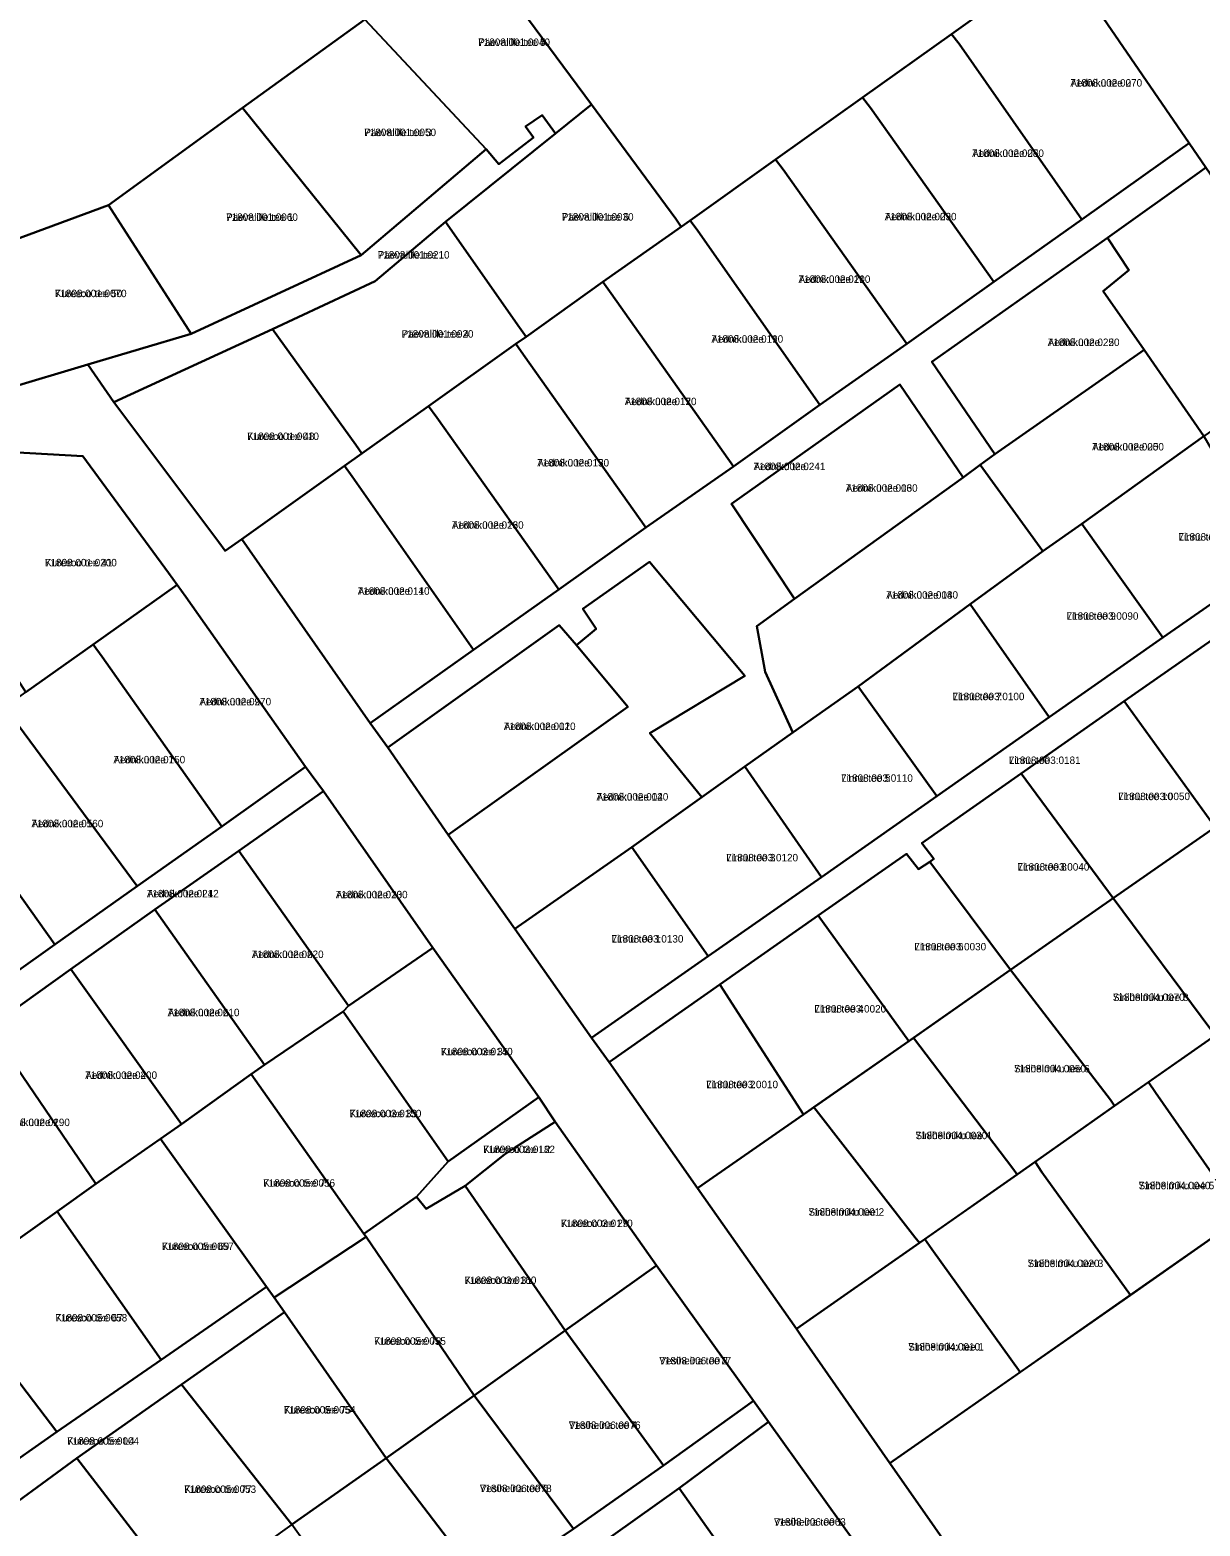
# Model space of a CAD drawing. Extents: x 529768 to 552006, y 6562269 to 6580975.
# Drawn here: x 537003.6 to 537239.9, y 6569673.6 to 6569975.7 of the extents above; entities that cross this region are included whole.
import ezdxf

# ---------------------------------------------------------------- set-up
doc = ezdxf.new("R2010")
doc.units = 0
for name, color, linetype in [('L_AADRESS', 7, 'Continuous'), ('PIIR', 7, 'Continuous'), ('TUNNUS', 7, 'Continuous')]:
    doc.layers.add(name, color=color, linetype=linetype)

msp = doc.modelspace()

# ---------------------------------------------------------------- linework, layer by layer
at = {"layer": 'PIIR'}
for points in [[(536874.54, 6569968.46), (536872.33, 6569970.82), (537004.98, 6570064.24), (537087.96, 6570044.75), (537217.62, 6570003.73), (537216.26, 6569994.13), (537211.8, 6569990.69), (537189.74, 6569974.89), (537171.78, 6569962.1), (537154.21, 6569949.58), (537136.95, 6569937.29), (537135.14, 6569936.01), (537134.04, 6569937.57), (537117.07, 6569960.7), (537092.75, 6569993.55), (537071.26, 6569977.87), (537046.54, 6569959.99), (537019.53, 6569940.36), (536982.49, 6569926.7), (536956.57, 6569916.92), (536936.23, 6569902.65)], [(537211.8, 6569990.69), (537216.26, 6569994.13), (537217.62, 6570003.73), (537232.49, 6570000.18), (537431.89, 6569969.31), (537436.12, 6569962.6), (537345.33, 6569804), (537340.93, 6569801.03), (537314.01, 6569841.27), (537303.21, 6569856.76), (537294.77, 6569869.2), (537282.21, 6569887.72), (537266.16, 6569911.4), (537241.1, 6569947.95), (537237.73, 6569952.86)], [(537092.75, 6569993.55), (537117.07, 6569960.7), (537109.79, 6569954.82), (537107.06, 6569958.54), (537103.75, 6569956.25), (537105.35, 6569953.99), (537098.33, 6569948.64), (537095.76, 6569951.67), (537071.26, 6569977.87)], [(537189.74, 6569974.89), (537211.8, 6569990.69), (537237.73, 6569952.86), (537236.38, 6569951.9), (537216.02, 6569937.45), (537191.29, 6569972.9)], [(537046.54, 6569959.99), (537071.26, 6569977.87), (537095.76, 6569951.67), (537070.53, 6569930.28)], [(537171.78, 6569962.1), (537189.74, 6569974.89), (537191.29, 6569972.9), (537216.02, 6569937.45), (537198.3, 6569924.84), (537173.36, 6569959.98)], [(537102.52, 6569915.64), (537087.53, 6569937.02), (537109.79, 6569954.82), (537117.07, 6569960.7), (537134.04, 6569937.57), (537135.14, 6569936.01), (537119.36, 6569924.86), (537103.82, 6569913.79)], [(537154.21, 6569949.58), (537171.78, 6569962.1), (537173.36, 6569959.98), (537198.3, 6569924.84), (537180.75, 6569912.38), (537155.75, 6569947.54)], [(537109.79, 6569954.82), (537087.53, 6569937.02), (537073.37, 6569924.99), (537052.62, 6569915.32), (537020.57, 6569900.6), (537015.35, 6569908.21), (537036.2, 6569914.4), (537070.53, 6569930.28), (537095.76, 6569951.67), (537098.33, 6569948.64), (537105.35, 6569953.99), (537103.75, 6569956.25), (537107.06, 6569958.54)], [(537019.53, 6569940.36), (537046.54, 6569959.99), (537070.53, 6569930.28), (537036.2, 6569914.4)], [(537115.26, 6569858.82), (537117.98, 6569854.8), (537114, 6569851.52), (537110.54, 6569855.53), (537075.93, 6569830.86), (537072.36, 6569835.79), (537093.24, 6569850.55), (537110.48, 6569862.75), (537128.03, 6569875.24), (537145.73, 6569887.59), (537163.14, 6569900.03), (537180.75, 6569912.38), (537198.3, 6569924.84), (537216.02, 6569937.45), (537236.38, 6569951.9), (537237.73, 6569952.86), (537241.1, 6569947.95), (537239.79, 6569947.01), (537221.23, 6569933.75), (537185.75, 6569908.75), (537198.5, 6569890.09), (537195.55, 6569887.91), (537192.06, 6569885.35), (537179.28, 6569904.13), (537145.28, 6569880.07), (537158.01, 6569860.85), (537150.46, 6569855.33), (537152.1, 6569846.14), (537157.71, 6569833.88), (537148.02, 6569827.01), (537139.3, 6569820.84), (537128.79, 6569833.71), (537148.02, 6569845.33), (537128.76, 6569868.32)], [(537136.95, 6569937.29), (537154.21, 6569949.58), (537155.75, 6569947.54), (537180.75, 6569912.38), (537163.14, 6569900.03), (537138.52, 6569935.16)], [(537228.61, 6569911.15), (537220.34, 6569923.01), (537225.55, 6569927.21), (537221.23, 6569933.75), (537239.79, 6569947.01), (537241.1, 6569947.95), (537266.16, 6569911.4), (537264.76, 6569910.44), (537240.71, 6569893.71)], [(536982.49, 6569926.7), (537019.53, 6569940.36), (537036.2, 6569914.4), (537015.35, 6569908.21), (536998.7, 6569903.2)], [(537069.43, 6569891.94), (537052.62, 6569915.32), (537073.37, 6569924.99), (537087.53, 6569937.02), (537102.52, 6569915.64), (537103.82, 6569913.79), (537101.78, 6569912.35), (537084.16, 6569899.8), (537070.68, 6569890.2)], [(537119.36, 6569924.86), (537135.14, 6569936.01), (537136.95, 6569937.29), (537138.52, 6569935.16), (537163.14, 6569900.03), (537145.73, 6569887.59), (537121.01, 6569922.53)], [(537225.55, 6569927.21), (537220.34, 6569923.01), (537228.61, 6569911.15), (537198.5, 6569890.09), (537185.75, 6569908.75), (537221.23, 6569933.75)], [(537101.78, 6569912.35), (537103.82, 6569913.79), (537119.36, 6569924.86), (537121.01, 6569922.53), (537145.73, 6569887.59), (537128.03, 6569875.24), (537103.34, 6569910.15)], [(537041.78, 6569872.29), (537020.57, 6569900.6), (537052.62, 6569915.32), (537069.43, 6569891.94), (537070.68, 6569890.2), (537067.2, 6569887.71), (537046.43, 6569872.94), (537043.08, 6569870.55)], [(537084.16, 6569899.8), (537101.78, 6569912.35), (537103.34, 6569910.15), (537128.03, 6569875.24), (537110.48, 6569862.75), (537085.81, 6569897.48)], [(537198.5, 6569890.09), (537228.61, 6569911.15), (537240.71, 6569893.71), (537216.03, 6569876.03), (537208.18, 6569870.5), (537195.55, 6569887.91)], [(537145.28, 6569880.07), (537179.28, 6569904.13), (537192.06, 6569885.35), (537158.01, 6569860.85)], [(537067.2, 6569887.71), (537070.68, 6569890.2), (537084.16, 6569899.8), (537085.81, 6569897.48), (537110.48, 6569862.75), (537093.24, 6569850.55), (537068.72, 6569885.54)], [(537216.03, 6569876.03), (537240.71, 6569893.71), (537255.1, 6569868.83), (537232.43, 6569853.06)], [(537001.14, 6569844.61), (536979.97, 6569876.46), (537000.05, 6569890.46), (537014.36, 6569889.68), (537031.65, 6569866.11), (537033.41, 6569863.68), (537016.43, 6569851.67), (537002.85, 6569842.04)], [(537046.43, 6569872.94), (537067.2, 6569887.71), (537068.72, 6569885.54), (537093.24, 6569850.55), (537072.36, 6569835.79), (537047.97, 6569870.72)], [(537266.5, 6569869.46), (537244.56, 6569854.13), (537224.58, 6569840.19), (537203.79, 6569825.57), (537183.73, 6569811.56), (537186.15, 6569808.37), (537185.37, 6569807.78), (537183.1, 6569806.29), (537180.68, 6569809.37), (537162.8, 6569796.92), (537142.98, 6569782.98), (537120.6, 6569767.33), (537117.06, 6569772.21), (537140.59, 6569788.71), (537163.51, 6569804.69), (537186.78, 6569821.01), (537209.48, 6569836.96), (537232.43, 6569853.06), (537255.1, 6569868.83), (537280.13, 6569886.27), (537282.21, 6569887.72), (537294.77, 6569869.2), (537292.95, 6569868.02), (537275.94, 6569857)], [(537208.18, 6569870.5), (537193.52, 6569859.79), (537170.88, 6569843.14), (537157.71, 6569833.88), (537152.1, 6569846.14), (537150.46, 6569855.33), (537158.01, 6569860.85), (537192.06, 6569885.35), (537195.55, 6569887.91)], [(537193.52, 6569859.79), (537208.18, 6569870.5), (537216.03, 6569876.03), (537232.43, 6569853.06), (537209.48, 6569836.96)], [(537088.07, 6569813.23), (537124.36, 6569839.05), (537114, 6569851.52), (537117.98, 6569854.8), (537115.26, 6569858.82), (537128.76, 6569868.32), (537148.02, 6569845.33), (537128.79, 6569833.71), (537139.3, 6569820.84), (537125.2, 6569810.72), (537101.58, 6569794.24)], [(537016.43, 6569851.67), (537033.41, 6569863.68), (537035.16, 6569861.27), (537059.3, 6569826.93), (537042.4, 6569814.87), (537018.21, 6569849.15)], [(537170.88, 6569843.14), (537193.52, 6569859.79), (537209.48, 6569836.96), (537186.78, 6569821.01)], [(537075.93, 6569830.86), (537110.54, 6569855.53), (537114, 6569851.52), (537124.36, 6569839.05), (537088.07, 6569813.23)], [(536998.59, 6569839.02), (537002.85, 6569842.04), (537016.43, 6569851.67), (537018.21, 6569849.15), (537042.4, 6569814.87), (537025.31, 6569802.87), (537000.4, 6569836.57)], [(537244.56, 6569854.13), (537263.28, 6569828.91), (537242.99, 6569814.75), (537224.58, 6569840.19)], [(537148.02, 6569827.01), (537157.71, 6569833.88), (537170.88, 6569843.14), (537186.78, 6569821.01), (537163.51, 6569804.69)], [(537224.58, 6569840.19), (537242.99, 6569814.75), (537222.41, 6569800.4), (537203.79, 6569825.57)], [(536982.61, 6569827.71), (536983.08, 6569828.05), (536998.59, 6569839.02), (537000.4, 6569836.57), (537025.31, 6569802.87), (537008.71, 6569791.05), (536984.39, 6569825.21)], [(536965.89, 6569815.87), (536982.61, 6569827.71), (536984.39, 6569825.21), (537008.71, 6569791.05), (536991.72, 6569779.05), (536967.63, 6569813.38)], [(537062.94, 6569822.02), (537045.82, 6569810), (537028.9, 6569798.1), (537011.91, 6569786.06), (536995.4, 6569774.32), (536990.47, 6569774.25), (536991.72, 6569779.05), (537008.71, 6569791.05), (537025.31, 6569802.87), (537042.4, 6569814.87), (537059.3, 6569826.93)], [(537125.2, 6569810.72), (537139.3, 6569820.84), (537148.02, 6569827.01), (537163.51, 6569804.69), (537140.59, 6569788.71)], [(537186.15, 6569808.37), (537183.73, 6569811.56), (537203.79, 6569825.57), (537222.41, 6569800.4), (537201.67, 6569785.93), (537185.37, 6569807.78)], [(537062.94, 6569822.02), (537084.99, 6569790.38), (537067.99, 6569778.67), (537045.82, 6569810)], [(537242.12, 6569773.91), (537222.41, 6569800.4), (537242.99, 6569814.75), (537262.44, 6569788.16), (537263.28, 6569786.91), (537251.54, 6569778.68), (537242.97, 6569772.67)], [(537045.82, 6569810), (537067.99, 6569778.67), (537066.88, 6569777.52), (537051.02, 6569766.75), (537028.9, 6569798.1)], [(537101.58, 6569794.24), (537125.2, 6569810.72), (537140.59, 6569788.71), (537117.06, 6569772.21)], [(537180.68, 6569809.37), (537183.1, 6569806.29), (537185.37, 6569807.78), (537201.67, 6569785.93), (537181.09, 6569771.58), (537162.8, 6569796.92)], [(537201.67, 6569785.93), (537222.41, 6569800.4), (537242.12, 6569773.91), (537242.97, 6569772.67), (537222.68, 6569758.46), (537221.82, 6569759.69)], [(537028.9, 6569798.1), (537051.02, 6569766.75), (537048.31, 6569764.87), (537034.25, 6569754.81), (537011.91, 6569786.06)], [(537162.8, 6569796.92), (537181.09, 6569771.58), (537159.82, 6569756.74), (537142.98, 6569782.98)], [(537066.88, 6569777.52), (537067.99, 6569778.67), (537084.99, 6569790.38), (537106.38, 6569760.22), (537088.07, 6569747.27)], [(537011.91, 6569786.06), (537034.25, 6569754.81), (537016.97, 6569742.76), (536995.4, 6569774.32)], [(537202.09, 6569745.84), (537182.04, 6569772.24), (537201.67, 6569785.93), (537221.82, 6569759.69), (537222.68, 6569758.46), (537206.61, 6569747.18), (537202.98, 6569744.63)], [(537120.6, 6569767.33), (537142.98, 6569782.98), (537159.82, 6569756.74), (537138.47, 6569741.85)], [(537051.02, 6569766.75), (537066.88, 6569777.52), (537088.07, 6569747.27), (537081.68, 6569740.11), (537071.08, 6569732.65), (537048.31, 6569764.87)], [(537230.93, 6569761.18), (537229.54, 6569763.26), (537242.97, 6569772.67), (537251.54, 6569778.68), (537252.71, 6569777.06), (537269.83, 6569751.11), (537248.43, 6569736.1)], [(536995.4, 6569774.32), (537016.97, 6569742.76), (537009.13, 6569737.15), (537001.22, 6569731.49), (536977.46, 6569765.04), (536990.47, 6569774.25)], [(537182.33, 6569732), (537161.94, 6569758.22), (537181.09, 6569771.58), (537182.04, 6569772.24), (537202.09, 6569745.84), (537202.98, 6569744.63), (537183.26, 6569730.81)], [(537034.25, 6569754.81), (537048.31, 6569764.87), (537071.08, 6569732.65), (537071.52, 6569732.03), (537052.96, 6569719.78), (537051.45, 6569721.95), (537030, 6569751.84)], [(537208.01, 6569745.12), (537206.61, 6569747.18), (537222.68, 6569758.46), (537229.54, 6569763.26), (537230.93, 6569761.18), (537248.43, 6569736.1), (537225.86, 6569720.29)], [(537088.07, 6569747.27), (537106.38, 6569760.22), (537109.74, 6569755.26), (537101.51, 6569750.01), (537099.45, 6569748.66), (537091.55, 6569742.31), (537083.66, 6569737.68), (537081.68, 6569740.11)], [(537157.15, 6569715.29), (537138.47, 6569741.85), (537159.82, 6569756.74), (537161.94, 6569758.22), (537182.33, 6569732), (537183.26, 6569730.81), (537158.41, 6569713.44)], [(537099.45, 6569748.66), (537101.51, 6569750.01), (537109.74, 6569755.26), (537130.19, 6569726.27), (537111.74, 6569713.13), (537091.55, 6569742.31)], [(537016.97, 6569742.76), (537030, 6569751.84), (537051.45, 6569721.95), (537030.15, 6569707.21), (537009.13, 6569737.15)], [(537185.79, 6569729.52), (537184.37, 6569731.57), (537202.98, 6569744.63), (537206.61, 6569747.18), (537208.01, 6569745.12), (537225.86, 6569720.29), (537203.61, 6569704.68)], [(537071.08, 6569732.65), (537081.68, 6569740.11), (537083.66, 6569737.68), (537091.55, 6569742.31), (537111.74, 6569713.13), (537093.32, 6569700.01), (537071.52, 6569732.03)], [(537001.22, 6569731.49), (537009.13, 6569737.15), (537030.15, 6569707.21), (537009.06, 6569692.64), (536987.43, 6569721.06)], [(537052.96, 6569719.78), (537071.52, 6569732.03), (537093.32, 6569700.01), (537075.56, 6569687.37), (537055.02, 6569716.81)], [(537159.51, 6569711.83), (537158.41, 6569713.44), (537183.26, 6569730.81), (537184.37, 6569731.57), (537185.79, 6569729.52), (537203.61, 6569704.68), (537177.27, 6569686.31)], [(537130.19, 6569726.27), (537149.74, 6569698.95), (537131.6, 6569685.88), (537111.74, 6569713.13)], [(536972.41, 6569658.2), (536968.13, 6569664.07), (536989.07, 6569678.69), (537009.06, 6569692.64), (537030.15, 6569707.21), (537051.45, 6569721.95), (537052.96, 6569719.78), (537055.02, 6569716.81), (537034.25, 6569702.21), (537013.11, 6569687.36), (536994.16, 6569673.46)], [(536968.79, 6569707.74), (536983.52, 6569718.1), (536987.43, 6569721.06), (537009.06, 6569692.64), (536989.07, 6569678.69)], [(537055.02, 6569716.81), (537075.56, 6569687.37), (537056.52, 6569673.94), (537034.25, 6569702.21)], [(537131.6, 6569685.88), (537113.43, 6569673.07), (537093.32, 6569700.01), (537111.74, 6569713.13)], [(537034.25, 6569702.21), (537056.52, 6569673.94), (537035.22, 6569658.65), (537013.11, 6569687.36)], [(537149.74, 6569698.95), (537152.81, 6569694.66), (537134.74, 6569681.28), (537116.99, 6569668.66), (537099.09, 6569656.2), (537079.39, 6569642.24), (537062.78, 6569630.47), (537047.13, 6569619.41), (537031.67, 6569608.68), (537015.83, 6569597.61), (537012.9, 6569601.76), (537028.62, 6569613.04), (537044.19, 6569623.89), (537059.55, 6569634.95), (537076.02, 6569646.54), (537095.55, 6569661.17), (537113.43, 6569673.07), (537131.6, 6569685.88)], [(537093.32, 6569700.01), (537113.43, 6569673.07), (537095.55, 6569661.17), (537075.56, 6569687.37)], [(537173.03, 6569666.4), (537154.76, 6569653.04), (537134.74, 6569681.28), (537152.81, 6569694.66)], [(537013.11, 6569687.36), (537035.22, 6569658.65), (537015.37, 6569644.51), (536994.16, 6569673.46)], [(537075.56, 6569687.37), (537095.55, 6569661.17), (537076.02, 6569646.54), (537056.52, 6569673.94)], [(537154.76, 6569653.04), (537137.51, 6569640.87), (537116.99, 6569668.66), (537134.74, 6569681.28)]]:
    msp.add_lwpolyline(points, close=True, dxfattribs=at)
for points in [[(536998.7, 6569903.2), (537015.35, 6569908.21), (537020.57, 6569900.6), (537041.78, 6569872.29), (537043.08, 6569870.55), (537046.43, 6569872.94), (537047.97, 6569870.72), (537072.36, 6569835.79), (537075.93, 6569830.86), (537088.07, 6569813.23), (537101.58, 6569794.24), (537117.06, 6569772.21), (537120.6, 6569767.33), (537138.47, 6569741.85), (537157.15, 6569715.29), (537158.41, 6569713.44), (537159.51, 6569711.83), (537177.27, 6569686.31), (537213.13, 6569635.04)], [(537173.03, 6569666.4), (537152.81, 6569694.66), (537149.74, 6569698.95), (537130.19, 6569726.27), (537109.74, 6569755.26), (537106.38, 6569760.22), (537084.99, 6569790.38), (537062.94, 6569822.02), (537059.3, 6569826.93), (537035.16, 6569861.27), (537033.41, 6569863.68), (537031.65, 6569866.11), (537014.36, 6569889.68), (537000.05, 6569890.46)], [(537266.4, 6569673.05), (537213.13, 6569635.04), (537177.27, 6569686.31), (537203.34, 6569704.49), (537225.59, 6569720.1), (537248.43, 6569736.1)]]:
    msp.add_lwpolyline(points, dxfattribs=at)

# ---------------------------------------------------------------- texts
at = {"layer": 'L_AADRESS'}
for s, p in [('Päevalille tee 5', (537094.16, 6569972.51)), ('Aedniku tee 27', (537213.73, 6569964.3)), ('Päevalille tee 3', (537071.15, 6569954.3)), ('Aedniku tee 25', (537193.9, 6569950.1)), ('Päevalille tee 1', (537043.25, 6569937.19)), ('Päevalille tee 6', (537111.04, 6569937.24)), ('Aedniku tee 23', (537176.25, 6569937.3)), ('Päevalille tee', (537073.88, 6569929.57)), ('Aedniku tee 21', (537158.85, 6569924.67)), ('Kuresoo tee 50', (537008.67, 6569921.78)), ('Päevalille tee 4', (537078.71, 6569913.61)), ('Aedniku tee 19', (537141.25, 6569912.59)), ('Aedniku tee 22', (537209.16, 6569911.92)), ('Aedniku tee 17', (537123.75, 6569899.97)), ('Kuresoo tee 48', (537047.51, 6569892.94)), ('Aedniku tee 20', (537218.12, 6569890.82)), ('Aedniku tee 15', (537106.09, 6569887.59)), ('Aedniku tee', (537149.77, 6569886.85)), ('Aedniku tee 16', (537168.39, 6569882.49)), ('Aedniku tee 13', (537088.84, 6569875.02)), ('Linnu tee 11', (537235.57, 6569872.63)), ('Kuresoo tee 41', (537006.69, 6569867.43)), ('Aedniku tee 11', (537069.84, 6569861.68)), ('Aedniku tee 18', (537176.55, 6569860.9)), ('Linnu tee 9', (537212.98, 6569856.64)), ('Aedniku tee 9', (537037.86, 6569839.36)), ('Linnu tee 7', (537189.96, 6569840.4)), ('Aedniku tee 12', (537099.33, 6569834.38)), ('Aedniku tee 7', (537020.5, 6569827.65)), ('Linnu tee', (537201.31, 6569827.52)), ('Linnu tee 5', (537167.43, 6569823.92)), ('Aedniku tee 14', (537118.05, 6569820.14)), ('Linnu tee 10', (537223.39, 6569820.22)), ('Aedniku tee 5', (537003.96, 6569814.74)), ('Linnu tee 3', (537144.25, 6569807.86)), ('Linnu tee 8', (537203.07, 6569805.99)), ('Aedniku tee L1', (537027.27, 6569800.59)), ('Aedniku tee 10', (537065.41, 6569800.4)), ('Linnu tee 1', (537121.1, 6569791.46)), ('Linnu tee 6', (537182.23, 6569789.88)), ('Aedniku tee 8', (537048.45, 6569788.34)), ('Linnu tee 4', (537162.04, 6569777.33)), ('Sinihelmiku tee 8', (537222.32, 6569779.66)), ('Aedniku tee 6', (537031.46, 6569776.59)), ('Kuresoo tee 35', (537086.63, 6569768.7)), ('Sinihelmiku tee 6', (537202.36, 6569765.25)), ('Aedniku tee 4', (537014.82, 6569763.94)), ('Linnu tee 2', (537140.21, 6569762.05)), ('Aedniku tee 2', (536997.21, 6569754.4)), ('Kuresoo tee 33', (537068.19, 6569756.19)), ('Sinihelmiku tee 4', (537182.46, 6569751.76)), ('Kuresoo tee L2', (537095.17, 6569748.95)), ('Kuresoo tee 71', (537050.76, 6569742.16)), ('Sinihelmiku tee 5', (537227.52, 6569741.65)), ('Sinihelmiku tee 2', (537160.86, 6569736.31)), ('Kuresoo tee 29', (537110.87, 6569734.02)), ('Kuresoo tee 69', (537030.29, 6569729.37)), ('Sinihelmiku tee 3', (537205.11, 6569725.93)), ('Kuresoo tee 31', (537091.41, 6569722.52)), ('Kuresoo tee 67', (537008.79, 6569714.95)), ('Kuresoo tee 73', (537073.14, 6569710.24)), ('Sinihelmiku tee 1', (537181.01, 6569709.08)), ('Vesiheina tee 2', (537130.74, 6569706.28)), ('Kuresoo tee 75', (537054.91, 6569696.36)), ('Vesiheina tee 4', (537112.46, 6569693.26)), ('Kuresoo tee L4', (537011.18, 6569690.07)), ('Kuresoo tee 77', (537034.82, 6569680.33)), ('Vesiheina tee 6', (537094.5, 6569680.49)), ('Vesiheina tee 1', (537153.89, 6569673.72))]:
    msp.add_text(s, height=1.5, dxfattribs=at).set_placement(p)
at = {"layer": 'TUNNUS'}
for s, p in [('71808:001:0040', (537094.16, 6569972.51)), ('71808:002:0070', (537213.73, 6569964.3)), ('71808:001:0050', (537071.15, 6569954.3)), ('71808:002:0080', (537193.9, 6569950.1)), ('71808:001:0060', (537043.25, 6569937.19)), ('71808:001:0030', (537111.04, 6569937.24)), ('71808:002:0090', (537176.25, 6569937.3)), ('71808:001:0210', (537073.88, 6569929.57)), ('71808:002:0100', (537158.85, 6569924.67)), ('71808:001:0070', (537008.67, 6569921.78)), ('71808:001:0020', (537078.71, 6569913.61)), ('71808:002:0110', (537141.25, 6569912.59)), ('71808:002:0250', (537209.16, 6569911.92)), ('71808:002:0120', (537123.75, 6569899.97)), ('71808:001:0010', (537047.51, 6569892.94)), ('71808:002:0050', (537218.12, 6569890.82)), ('71808:002:0130', (537106.09, 6569887.59)), ('71808:002:0241', (537149.77, 6569886.85)), ('71808:002:0030', (537168.39, 6569882.49)), ('71808:002:0260', (537088.84, 6569875.02)), ('71808:003:0080', (537235.57, 6569872.63)), ('71808:001:0200', (537006.69, 6569867.43)), ('71808:002:0140', (537069.84, 6569861.68)), ('71808:002:0040', (537176.55, 6569860.9)), ('71808:003:0090', (537212.98, 6569856.64)), ('71808:002:0270', (537037.86, 6569839.36)), ('71808:003:0100', (537189.96, 6569840.4)), ('71808:002:0010', (537099.33, 6569834.38)), ('71808:002:0150', (537020.5, 6569827.65)), ('71808:003:0181', (537201.31, 6569827.52)), ('71808:003:0110', (537167.43, 6569823.92)), ('71808:002:0020', (537118.05, 6569820.14)), ('71808:003:0050', (537223.39, 6569820.22)), ('71808:002:0160', (537003.96, 6569814.74)), ('71808:003:0120', (537144.25, 6569807.86)), ('71808:003:0040', (537203.07, 6569805.99)), ('71808:002:0242', (537027.27, 6569800.59)), ('71808:002:0230', (537065.41, 6569800.4)), ('71808:003:0130', (537121.1, 6569791.46)), ('71808:003:0030', (537182.23, 6569789.88)), ('71808:002:0220', (537048.45, 6569788.34)), ('71808:004:0070', (537222.32, 6569779.66)), ('71808:002:0210', (537031.46, 6569776.59)), ('71808:003:0020', (537162.04, 6569777.33)), ('71808:003:0140', (537086.63, 6569768.7)), ('71808:002:0200', (537014.82, 6569763.94)), ('71808:004:0050', (537202.36, 6569765.25)), ('71808:003:0010', (537140.21, 6569762.05)), ('71808:002:0190', (536997.21, 6569754.4)), ('71808:003:0150', (537068.19, 6569756.19)), ('71808:004:0030', (537182.46, 6569751.76)), ('71808:003:0182', (537095.17, 6569748.95)), ('71808:005:0056', (537050.76, 6569742.16)), ('71808:004:0040', (537227.52, 6569741.65)), ('71808:004:0001', (537160.86, 6569736.31)), ('71808:003:0170', (537110.87, 6569734.02)), ('71808:005:0057', (537030.29, 6569729.37)), ('71808:004:0020', (537205.11, 6569725.93)), ('71808:003:0160', (537091.41, 6569722.52)), ('71808:005:0058', (537008.79, 6569714.95)), ('71808:005:0055', (537073.14, 6569710.24)), ('71808:004:0010', (537181.01, 6569709.08)), ('71808:006:0077', (537130.74, 6569706.28)), ('71808:005:0054', (537054.91, 6569696.36)), ('71808:006:0076', (537112.46, 6569693.26)), ('71808:005:0004', (537011.18, 6569690.07)), ('71808:005:0053', (537034.82, 6569680.33)), ('71808:006:0078', (537094.5, 6569680.49)), ('71808:006:0063', (537153.89, 6569673.72))]:
    msp.add_text(s, height=1.5, dxfattribs=at).set_placement(p)

doc.saveas('drawing.dxf')
